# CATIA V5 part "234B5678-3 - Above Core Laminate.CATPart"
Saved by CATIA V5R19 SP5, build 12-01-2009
Part number: 234B5678-3 - Above Core Laminate
Publications: "Layup for systems"
Bounding box of the stored display mesh (mm): x 31564.691 to 31910.885, y -11350.452 to -11180.56, z 5296.563 to 5471.49
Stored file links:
  C:\Users\rem1927\Desktop\Current Explicit Composite Demo\234B5678-3 - Above Core Laminate.CATPart
  C:\Users\rem1927\Desktop\Current Explicit Composite Demo\234B5678-1 Composite Product.CATProduct
  C:\Users\rem1927\Desktop\Tess Product Demo R20\Catalog_TNA.CATMaterial
  C:\Users\rem1927\Desktop\Tess Product Demo R20\234B5678_2_Rev_.CATPart
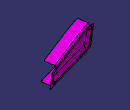
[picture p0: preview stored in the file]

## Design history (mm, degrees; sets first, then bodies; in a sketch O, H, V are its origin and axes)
CompParametersFeature1 "CATCoParametersFeatName": Value 0, Value 45, Value -45, Value 90, default 0
AxisSystem1 "Rosette Above": origin (31647.2934, -11263.1074, 5379.7103), X (0.9552, 0.2927, -0.0445), Y (0, 0.1502, 0.9887), Z (0.2961, -0.9443, 0.1435)
CompStacking1 "Stacking"
Set1 "Construction"
  Offset1 "Above Core Layup Surface": Offset DatumSurface1, Length 0
  Intersect1: ToIntersect1 Offset1, ToIntersect2 DatumSurface2
  Intersect2: ToIntersect1 Offset1, ToIntersect2 DatumSurface3
  Intersect3: ToIntersect1 Offset1, ToIntersect2 DatumSurface4
  Intersect4: ToIntersect1 Offset1, ToIntersect2 DatumSurface5
  Corner1: Element1 Intersect1, Element2 Intersect4, Support Offset1, Radius 6.35
  Corner2: Element1 Corner1, Element2 Intersect2, Support Offset1, Radius 6.35
  Corner3: Element1 Corner2, Element2 Intersect3, Support Offset1, Radius 6.35
  Corner4: Element1 Corner3, Element2 Intersect3, Support Offset1, Radius 6.35
  Split1: ToCut Intersect3, Cutting Corner4
  Join1 "EOP - Above Plys": Elements (Corner4; Split1)
  Split2 "Solid Base Surface": ToCut Offset1, Cutting Join1
  Offset2 "Layup for systems": Offset Split2, Length 1.5088
Set2 "Ply Group 2"
  Set3 "Sequence 200"
    Set4 "Ply 200"
      CLDGeom1 "Ply 200 Geometry"
  Set5 "Sequence 210"
    Set6 "Ply 210"
      CLDGeom2 "Ply 210 Geometry"
  Set7 "Sequence 220"
    Set8 "Ply 220"
      CLDGeom3 "Ply 220 Geometry"
Set9 "Rosette Construction"
  Intersect5: ToIntersect1 DatumCurve1, ToIntersect2 DatumCurve2
Set10
  DatumSurface1 "Top of Core IML": linked copy from another document
  DatumSurface2 "aft_trim_surface": linked copy from another document
  DatumSurface3 "fwd_trim_surface": linked copy from another document
  DatumSurface4 "Flange 1 Intersect": linked copy from another document
  DatumSurface5 "Flange 2 Intersect": linked copy from another document
  DatumCurve1 "Rose 3": linked copy from another document
  DatumCurve2 "Rose 2": linked copy from another document
  DatumCurve3 "Rose 1": linked copy from another document
  DatumPoint1 "Rose 4": linked copy from another document
  Plane1 "reference_plane": linked copy from another document
Body1 (main body)
Body2 "Ply 10"
  ThickSurface1: BotOffset 0, Surface Split2, TopOffset 0.254
Body3 "Ply 11"
  ThickSurface2: BotOffset -0.254, Surface Split2, TopOffset 0.508
Body4 "Ply 12"
  ThickSurface3: BotOffset -0.508, Surface Split2, TopOffset 1.5088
